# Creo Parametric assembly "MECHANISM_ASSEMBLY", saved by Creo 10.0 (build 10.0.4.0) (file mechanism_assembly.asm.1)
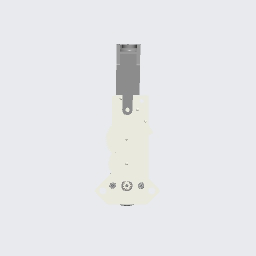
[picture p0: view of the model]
Units: millimeter Kilogram Sec (mmKs); MM, KILOGRAM, SECS

Created from: XX_MMKS_ASM_DESIGN_ABS.ASM

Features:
  1. datum plane "ASM_RIGHT"
  2. datum plane "ASM_TOP"
  3. datum plane "ASM_FRONT"
  4. coordinate system
  5. component "INTERNAL_FRAME"
  6. component "56_GEAR"
  7. component "64_GEAR"
  8. component "SECTOR_SHAPED_GEAR", "DRIVE.PRT"
  9. component "PLASTIC_NOOZLE_PIECE", "PRT0001.PRT"
  10. component "MOTOR"
  11. component "PIN_ASSEM"
  12. component "INNER_SCREW_M2_5"
  13. component "INNER_SCREW_M2_5"

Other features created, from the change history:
  component "56_GEAR.PRT"
  component "PRT0001.PRT" (2 times)
  sketch "Sketch 1"
  component "MOTOR_ASSEMBLY.ASM"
